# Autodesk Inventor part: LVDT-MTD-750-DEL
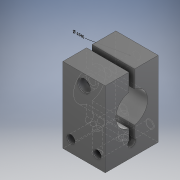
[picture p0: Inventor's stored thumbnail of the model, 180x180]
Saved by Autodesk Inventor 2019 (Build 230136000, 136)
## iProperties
Created: 2018-06
Part Number: LVDT-MTD-750-DEL
Material: Acetal Resin, Black
Document SubType Name: Modeling
Designer: Justin
Density: 1.425 g/cm^3
Appearance: Smooth - Black
Author: Justin
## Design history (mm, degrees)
node "Annotations"
  node "Diameter Dimension 1" dims "d0" = 25.4, "d1" = 45.212, "d67" = 4.1656 (derived)
sketch "Sketch1"
  geometry: L1 (12.7, 22.606)-(-12.7, 22.606); L2 (-12.7, 22.606)-(-12.7, -22.606); L3 (-12.7, -22.606)-(12.7, -22.606); L4 (12.7, -22.606)-(12.7, 22.606); L5 (12.7, 22.606)-(-12.7, -22.606); L6 (-12.7, 22.606)-(12.7, -22.606); 1 further point
  constraints: 12 end point, 2 midpoint, 2 parallel, 1 horizontal, 1 perpendicular
  dimensions: "d0" = 25.4 distance of L3.end L2.end; "d1" = 45.212 distance of L2.end L1.end
extrude "Extrusion1" new body sketch "Sketch1" stored distance "d2" = 31.75; taper "d3" = 0 deg
sketch "Sketch2"
  geometry: L1 (15.875, 22.606)-(15.875, 45.27); L2 (31.75, 0)-(0, 0) reference; C1 r 9.525 at (15.875, 25.4)
  constraints: 2 end point, 1 centre point, 1 point on line, 1 vertical
  dimensions: "d4" = 19.05 diameter of C1; "d5" = 25.4 distance from line of L2 C1.centre
extrude "Extrusion2" cut sketch "Sketch2" distance "d6" = 31.75; taper "d7" = 0 deg
sketch "Sketch3"
  geometry: L1 (15.875, 22.606)-(15.875, 51.723); L2 (17.526, 22.606)-(17.526, 51.723); L3 (14.224, 22.606)-(14.224, 51.723); L4 (14.224, 47.407)-(17.526, 47.407); L5 (14.224, 22.606)-(17.526, 22.606)
  constraints: 10 end point, 3 parallel, 2 point on line, 1 horizontal, 1 vertical
  dimensions: "d8" = 1.651 distance between parallel lines of L1 L2; "d9" = 1.651 distance between parallel lines of L1 L3
extrude "Extrusion3" cut sketch "Sketch3" distance "d10" = 31.75; taper "d11" = 0 deg
sketch "Sketch4"
  geometry: L1 (0, -31.75)-(25.4, -31.75) reference; L2 (12.7, -31.75)-(12.7, 0); L3 (0, 0)-(25.4, 0) reference; 3 further points
  constraints: 2 end point, 2 midpoint, 2 point on line
  dimensions: "d12" = 7.874 distance of point (12.7, -8.001) point (12.7, -15.875); "d13" = 7.874 distance of point (12.7, -15.875) point (12.7, -23.749)
hole "Hole1" sketch "Sketch4" at (12.7, -8.001), (12.7, -23.749) diameter "d14" = 4.1656; stored, may be unused: countersink angle "d18" = 82 deg, drill point angle "d20" = 118 deg; dims "d15" = 8.3312, "d16" = 9.525, "d17" = 6.35, "d19" = 12.7
sketch "Sketch5"
  geometry: L1 (0, 0)-(31.75, 0) reference; L2 (15.875, 7.874)-(15.875, 49.236); L3 (14.224, 9.634)-(14.224, 18.509); L4 (17.526, 9.634)-(17.526, 18.509); L5 (14.224, 18.509)-(17.526, 18.509); A1 r 2.413 centre (15.875, 7.874) between (14.224, 9.634) and (17.526, 9.634); 1 further point
  constraints: 8 end point, 2 parallel, 2 point on circle, 1 centre point, 1 horizontal, 1 vertical
  dimensions: "d21" = 4.826 diameter of A1; "d22" = 7.874 distance from line of L1 L2.start; "d23" = 1.651 distance between parallel lines of L2 L3; "d24" = 1.651 distance between parallel lines of L2 L4
extrude "Extrusion4" cut sketch "Sketch5" distance "d25" = 31.75; taper "d26" = 0 deg
sketch "Sketch6"
  geometry: L1 (-22.789, -15.469)-(42.546, -15.469); L2 (-22.789, -15.469)-(42.546, -15.469); L3 (-12.7, -22.606)-(12.7, -22.606) reference; L4 (0, 0)-(0, -28.093); 2 further points
  constraints: 6 end point, 2 point on line, 1 collinear, 1 horizontal, 1 symmetric about line, 1 vertical
  dimensions: "d28" = 7.1374 distance between parallel lines of L3 L1; "d29" = 15.748 distance of point (7.874, -15.469) point (-7.874, -15.469)
hole "Hole2" sketch "Sketch6" at (-7.874, -15.469), (7.874, -15.469) diameter "d30" = 4.318; stored, may be unused: countersink angle "d34" = 82 deg, drill point angle "d36" = 0 deg; dims "d31" = 8.3312, "d32" = 9.525, "d33" = 6.35, "d35" = 12.7
sketch "Sketch7"
  geometry: L1 (0, 0)-(0, 29.263); L2 (12.7, 22.606)-(-12.7, 22.606) reference; 1 further point
  constraints: 2 end point, 1 point on line, 1 vertical
  dimensions: "d37" = 6.35 distance from line of L2 point (0, 16.256)
hole "Hole3" sketch "Sketch7" at (0, 16.256) diameter "d38" = 4.318; stored, may be unused: countersink angle "d42" = 82 deg, drill point angle "d44" = 0 deg; dims "d39" = 12.7, "d40" = 7.112, "d41" = 4.953, "d43" = 12.7
sketch "Sketch8"
  geometry: L1 (-25.4, 10.431)-(0, 10.431) reference; L2 (-12.7, 10.431)-(-12.7, -34.781); L3 (-10.617, -34.781)-(-14.783, -34.781) reference; 2 further points
  constraints: 3 midpoint, 2 end point, 1 point on line
  dimensions: "d45" = 6.35 distance from line of L1 point (-12.7, 4.081)
hole "Hole4" sketch "Sketch8" at (-12.7, 4.081) diameter "d46" = 4.1656; stored, may be unused: countersink angle "d50" = 82 deg, drill point angle "d52" = 0 deg; dims "d47" = 8.3312, "d48" = 7.112, "d49" = 4.953, "d51" = 12.2936
chamfer "Chamfer1" distance "d55" = 0.3175; stored, may be unused: second distance "d56" = 3.175, angle "d57" = 45 deg
chamfer "Chamfer2" distance "d58" = 0.3175; stored, may be unused: second distance "d59" = 3.175, angle "d60" = 45 deg
chamfer "Chamfer3" distance "d61" = 0.3175; stored, may be unused: second distance "d62" = 3.175, angle "d63" = 45 deg
body "Solid1"
other parameters: "d64" = 33.44256 (derived), "d65" = 8.87135 (derived), "d66" = 9.67572 (derived)
